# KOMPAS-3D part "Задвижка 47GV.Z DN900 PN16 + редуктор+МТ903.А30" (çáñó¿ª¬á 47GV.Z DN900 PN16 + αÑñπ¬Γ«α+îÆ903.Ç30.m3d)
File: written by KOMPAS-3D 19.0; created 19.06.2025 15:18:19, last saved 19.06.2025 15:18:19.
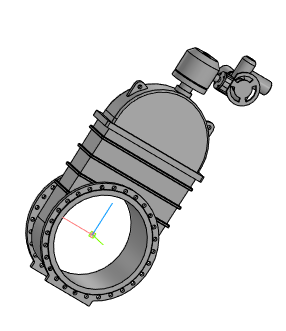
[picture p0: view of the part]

Document properties: Полное имя файла: Задвижка 47GV.Z DN900 PN16 + редуктор+МТ903.А30.a3d

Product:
- Part/product: Задвижка 47GV.Z DN900 PN16 + редуктор+МТ903.А30
    Масса: 3720.45

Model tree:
1. Операция без истории:1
